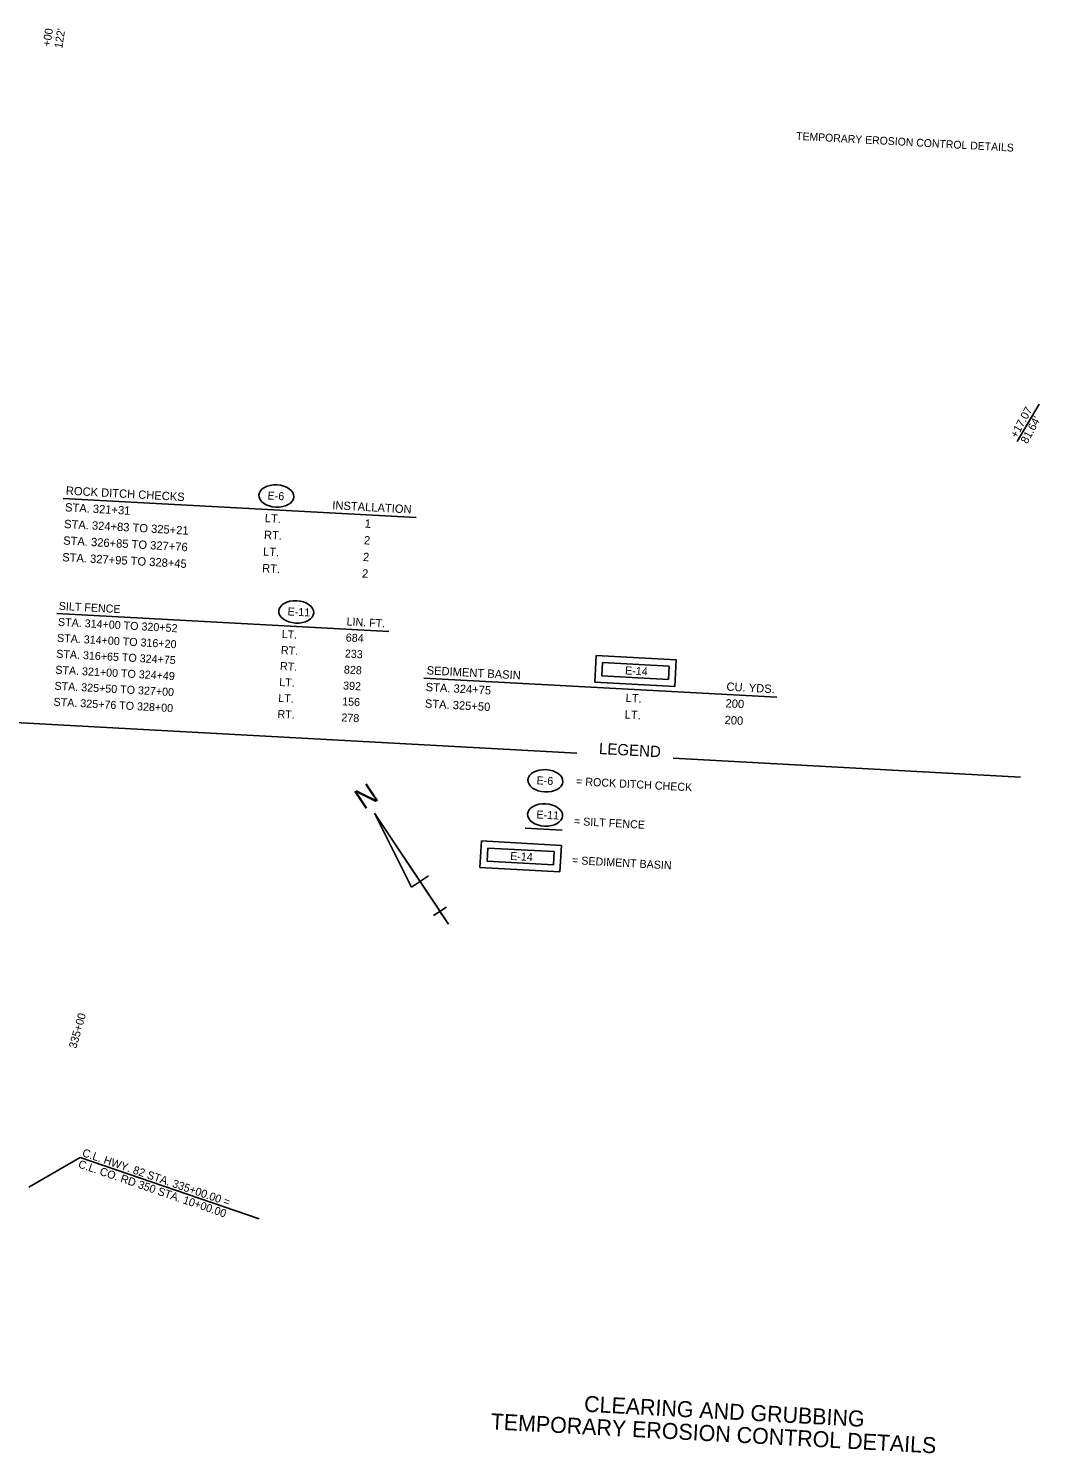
# Model space of a CAD drawing. Extents: x 881123 to 882718, y 1566283 to 1567356.
# Drawn here: x 881960 to 882718, y 1566283 to 1567351 of the extents above; entities that cross this region are included whole.
import ezdxf

# ---------------------------------------------------------------- set-up
doc = ezdxf.new("R2010")
doc.units = 0
for name, color, linetype in [('Default', 7, 'Continuous'), ('R_Border', 7, 'Continuous'), ('R_Border Prem', 7, 'Continuous'), ('R_Draft', 7, 'Continuous'), ('STAMP', 7, 'Continuous'), ('STAMP_PP', 7, 'Continuous')]:
    doc.layers.add(name, color=color, linetype=linetype)

msp = doc.modelspace()

# ---------------------------------------------------------------- linework, layer by layer
at = {"layer": 'Default'}
for p, q in [((881985.8, 1566998.5), (882250.5, 1566984.1)), ((882256.2, 1566863.8), (882520.9, 1566849.4))]:
    msp.add_line(p, q, dxfattribs=at)
at = {"layer": 'R_Border'}
msp.add_line((881981.2, 1566912.2), (882230.1, 1566898.6), dxfattribs=at)
msp.add_lwpolyline([(881960.1, 1566482.1), (881998.6, 1566504.4), (882132.9, 1566458.4)], dxfattribs=at)
at = {"layer": 'R_Border Prem'}
for p, q in [((882371, 1566807.6), (881924.2, 1566831.9)), ((882703.5, 1566789.5), (882443.2, 1566803.7)), ((882274.6, 1566679.3), (882219.3, 1566762.6)), ((882219.3, 1566762.6), (882261.9, 1566698.5)), ((882219.3, 1566762.6), (882247, 1566707)), ((882247, 1566707), (882259.8, 1566715.6)), ((882274.6, 1566679.3), (882261.9, 1566698.5)), ((882263.5, 1566685.7), (882273.1, 1566692.1)), ((882268.3, 1566688.9), (882263.5, 1566685.7)), ((882274.6, 1566679.3), (882268.3, 1566688.9))]:
    msp.add_line(p, q, dxfattribs=at)
at = {"layer": 'R_Draft'}
for p, q in [((882384.4, 1566860.8), (882385.5, 1566880.7)), ((882385.5, 1566880.7), (882445.4, 1566877.5)), ((882389.7, 1566865.5), (882390.2, 1566875.5)), ((882390.2, 1566875.5), (882440.2, 1566872.8)), ((882445.4, 1566877.5), (882444.3, 1566857.5)), ((882439.6, 1566862.8), (882389.7, 1566865.5)), ((882440.2, 1566872.8), (882439.6, 1566862.8)), ((882444.3, 1566857.5), (882384.4, 1566860.8)), ((882298.3, 1566721.7), (882299.4, 1566741.7)), ((882299.4, 1566741.7), (882359.3, 1566738.4)), ((882303.6, 1566726.5), (882304.1, 1566736.4)), ((882304.1, 1566736.4), (882354, 1566733.7)), ((882359.3, 1566738.4), (882358.2, 1566718.5)), ((882353.5, 1566723.7), (882303.6, 1566726.5)), ((882354, 1566733.7), (882353.5, 1566723.7)), ((882358.2, 1566718.5), (882298.3, 1566721.7))]:
    msp.add_line(p, q, dxfattribs=at)
msp.add_lwpolyline([(882332.2, 1566751.4), (882359.9, 1566749.9)], dxfattribs=at)
for centre in [(882145.7, 1567000.3), (882160.6, 1566913.4), (882347.3, 1566786.8), (882347.1, 1566761.2)]:
    msp.add_ellipse(centre, major_axis=(13.1, -0.7), ratio=0.638788, dxfattribs=at)
at = {"layer": 'STAMP'}
msp.add_line((882701, 1567041.1), (882717.4, 1567069.2), dxfattribs=at)

# ---------------------------------------------------------------- texts
at = {"layer": 'Default'}
for s, p in [('ROCK DITCH CHECKS', (881987.8, 1567001.3)), ('STA. 321+31', (881987.2, 1566988.8)), ('INSTALLATION', (882187.5, 1566990.4)), ('STA. 324+83 TO 325+21', (881986.5, 1566976.3)), ('LT.   ', (882136.9, 1566980.7)), ('1', (882211.8, 1566976.6)), ('RT.', (882136.3, 1566968.2)), ('STA. 326+85 TO 327+76', (881985.8, 1566963.9)), ('LT.', (882135.6, 1566955.7)), ('2', (882211.2, 1566964.1)), ('STA. 327+95 TO 328+45', (881985.1, 1566951.4)), ('RT.', (882134.9, 1566943.2)), ('2', (882210.5, 1566951.6)), ('2', (882209.8, 1566939.2)), ('SEDIMENT BASIN', (882258.2, 1566866.6)), ('STA. 324+75', (882257.5, 1566854.1)), ('CU. YDS. ', (882482.9, 1566854.4)), ('STA. 325+50', (882256.9, 1566841.7)), ('LT.', (882407.3, 1566846)), ('200', (882482.2, 1566841.9)), ('LT.', (882406.6, 1566833.5)), ('200', (882481.5, 1566829.4))]:
    msp.add_text(s, height=6.25, rotation=356.8871, dxfattribs=at).set_placement(p)
at = {"layer": 'R_Border'}
for s, height, rotation, p in [('SILT FENCE', 6, 356.8871, (881982.5, 1566915)), ('STA. 314+00 TO 320+52', 6, 356.8871, (881981.9, 1566903)), ('LIN. FT.', 6, 356.8871, (882198.2, 1566903.3)), ('STA. 314+00 TO 316+20', 6, 356.8871, (881981.2, 1566891)), ('LT. ', 6, 356.8871, (882149.6, 1566893.9)), ('684', 6, 356.8871, (882197.6, 1566891.3)), ('RT.', 6, 356.8871, (882149, 1566881.9)), ('233', 6, 356.8871, (882196.9, 1566879.3)), ('STA. 316+65 TO 324+75', 6, 356.8871, (881980.6, 1566879.1)), ('RT.', 6, 356.8871, (882148.3, 1566869.9)), ('STA. 321+00 TO 324+49', 6, 356.8871, (881979.9, 1566867.1)), ('LT.', 6, 356.8871, (882147.7, 1566857.9)), ('828', 6, 356.8871, (882196.2, 1566867.3)), ('E-14', 6, 356.8755, (882406.9, 1566866.6)), ('STA. 325+50 TO 327+00', 6, 356.8871, (881979.3, 1566855.1)), ('392', 6, 356.8871, (882195.6, 1566855.3)), ('STA. 325+76 TO 328+00', 6, 356.8871, (881978.6, 1566843.1)), ('LT.', 6, 356.8871, (882147, 1566846)), ('156', 6, 356.8871, (882194.9, 1566843.4)), ('RT.', 6, 356.8871, (882146.4, 1566834)), ('278', 6, 356.8871, (882194.3, 1566831.4)), ('E-14', 6, 356.8755, (882320.8, 1566727.5)), ('C.L. CO. RD 350 STA. 10+00.00', 6, 341.0675, (881996.7, 1566497.1)), ('C.L. HWY. 82 STA. 335+00.00 =', 6, 341.0675, (881999.7, 1566505.6)), ('CLEARING AND GRUBBING', 12, 356.8871, (882376.1, 1566313.9)), ('TEMPORARY EROSION CONTROL DETAILS', 12, 356.8871, (882306.1, 1566300.7))]:
    msp.add_text(s, height=height, rotation=rotation, dxfattribs=at).set_placement(p)
at = {"layer": 'R_Border Prem'}
for s, height, rotation, p in [('TEMPORARY EROSION CONTROL DETAILS', 5.862, 356.8871, (882535.1, 1567267.3)), ('N', 15.4, 33.5953, (882211.1, 1566764.8))]:
    msp.add_text(s, height=height, rotation=rotation, dxfattribs=at).set_placement(p)
at = {"layer": 'R_Draft'}
for s, height, rotation, p in [('E-6', 6, 357.1015, (882139, 1566997.7)), ('E-11', 6, 357.1015, (882154, 1566910.8)), ('LEGEND', 8.44, 356.8871, (882387.3, 1566806.9)), ('E-6', 6, 357.1015, (882340.6, 1566784.2)), ('= ROCK DITCH CHECK', 6, 356.8871, (882370.2, 1566783.6)), ('E-11', 6, 357.1015, (882340.5, 1566758.6)), ('= SILT FENCE', 6, 356.8871, (882368.6, 1566753.7)), ('= SEDIMENT BASIN', 6, 356.8871, (882367.2, 1566724.4))]:
    msp.add_text(s, height=height, rotation=rotation, dxfattribs=at).set_placement(p)
at = {"layer": 'STAMP'}
for s, rotation, p in [('+00', 81.2161, (881976.3, 1567336.9)), ("122'", 81.2161, (881985.2, 1567335.5)), ('+17.07', 61.2048, (882700.6, 1567043.3)), ("81.64'", 61.2048, (882708.4, 1567039))]:
    msp.add_text(s, height=6, rotation=rotation, dxfattribs=at).set_placement(p)
at = {"layer": 'STAMP_PP'}
msp.add_text('335+00', height=6, rotation=73.996, dxfattribs=at).set_placement((881995.7, 1566585.7))

doc.saveas('drawing.dxf')
